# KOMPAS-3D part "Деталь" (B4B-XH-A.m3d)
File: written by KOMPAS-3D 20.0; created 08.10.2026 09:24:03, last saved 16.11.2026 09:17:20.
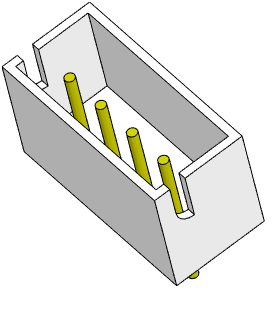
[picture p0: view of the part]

Document properties: Полное имя файла: D:\RicWork\Project-EPS32\box_compas\разъемы\B4B-XH-A.m3d

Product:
- Part/product: Деталь
    Масса: 0.00142227

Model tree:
1. Эскиз:1
2. Элемент выдавливания:1
     Расстояние 1 = 7
3. Эскиз:2  (with: Элемент выдавливания:1)
4. Эскиз:3  (with: Элемент выдавливания:1)
5. Элемент выдавливания:3
     Расстояние 2 = 12.4
6. Скругление:1  (with: Элемент выдавливания:3)
     Радиус = 1
7. Эскиз:4  (with: Элемент выдавливания:1)
8. Элемент выдавливания:4
     Расстояние 1 = 3.4
9. Массив по сетке:1  (with: Элемент выдавливания:4, Эскиз:4)  (4 pattern instances)
     Шаг 1 = 10; Угол раствора = -90; Шаг 2 = 2.54
10. Элемент выдавливания:6
     Расстояние 2 = 6
11. Эскиз:6  (with: Элемент выдавливания:6, Элемент выдавливания:1)
12. Элемент выдавливания:7
     Расстояние 1 = 5
13. Массив по сетке:2  (with: Элемент выдавливания:7, Эскиз:6)  (4 pattern instances)
     Шаг 1 = 10; Угол раствора = 90; Шаг 2 = 2.54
